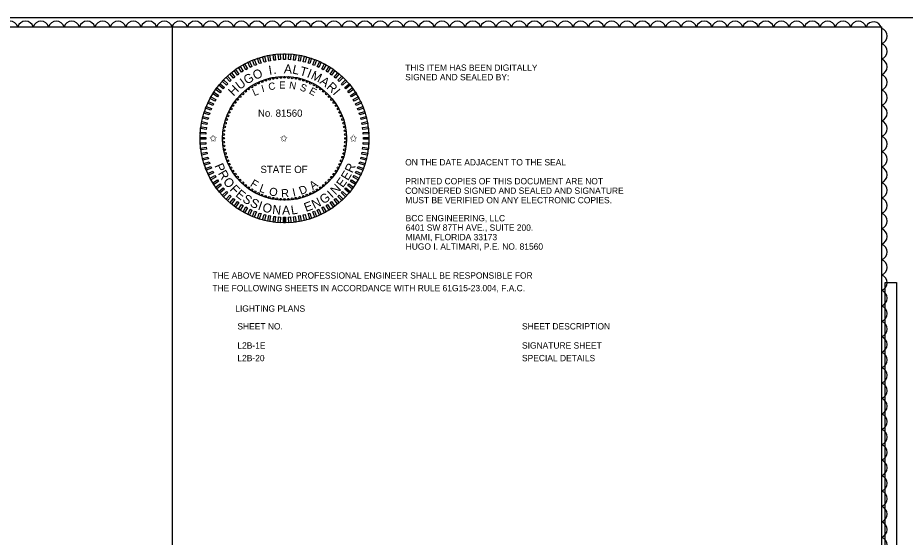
# Model space of a CAD drawing. Extents: x -816.9 to -790.1, y -2199.5 to -2188.9.
# Drawn here: x -804.97 to -795.12, y -2194.66 to -2188.9 of the extents above; entities that cross this region are included whole.
import ezdxf

# ---------------------------------------------------------------- set-up
doc = ezdxf.new("R2010")
doc.units = 0
for name, color, linetype in [('Cloud_dp', 7, 'Continuous'), ('Logo_dp', 7, 'Continuous'), ('NonPlottingEle_dp', 7, 'Continuous'), ('PlotBorder_dp', 7, 'Continuous'), ('ScratchEle_dp', 7, 'Continuous'), ('SheetBorder_dp', 7, 'Continuous'), ('TextMisc', 7, 'Continuous'), ('TextNotes', 7, 'Continuous')]:
    doc.layers.add(name, color=color, linetype=linetype)

msp = doc.modelspace()

# ---------------------------------------------------------------- linework, layer by layer
at = {"layer": 'Cloud_dp'}
for centre, radius, start, end in [((-805.0532, -2189.0276), 0.0897, 17.5, 162.5), ((-804.882, -2189.0276), 0.0897, 17.5, 162.5), ((-804.7109, -2189.0276), 0.0897, 17.5, 162.5), ((-804.5398, -2189.0276), 0.0897, 17.5, 162.5), ((-804.3687, -2189.0276), 0.0897, 17.5, 162.5), ((-804.1976, -2189.0276), 0.0897, 17.5, 162.5), ((-804.0264, -2189.0276), 0.0897, 17.5, 162.5), ((-803.8553, -2189.0276), 0.0897, 17.5, 162.5), ((-803.6842, -2189.0276), 0.0897, 17.5, 162.5), ((-803.5131, -2189.0276), 0.0897, 17.5, 162.5), ((-803.3419, -2189.0276), 0.0897, 17.5, 162.5), ((-803.1708, -2189.0276), 0.0897, 17.5, 162.5), ((-802.9997, -2189.0276), 0.0897, 17.5, 162.5), ((-802.8286, -2189.0276), 0.0897, 17.5, 162.5), ((-802.6575, -2189.0276), 0.0897, 17.5, 162.5), ((-802.4863, -2189.0276), 0.0897, 17.5, 162.5), ((-802.3152, -2189.0276), 0.0897, 17.5, 162.5), ((-802.1441, -2189.0276), 0.0897, 17.5, 162.5), ((-801.973, -2189.0276), 0.0897, 17.5, 162.5), ((-801.8018, -2189.0276), 0.0897, 17.5, 162.5), ((-801.6307, -2189.0276), 0.0897, 17.5, 162.5), ((-801.4596, -2189.0276), 0.0897, 17.5, 162.5), ((-801.2885, -2189.0276), 0.0897, 17.5, 162.5), ((-801.1174, -2189.0276), 0.0897, 17.5, 162.5), ((-800.9462, -2189.0276), 0.0897, 17.5, 162.5), ((-800.7751, -2189.0276), 0.0897, 17.5, 162.5), ((-800.604, -2189.0276), 0.0897, 17.5, 162.5), ((-800.4329, -2189.0276), 0.0897, 17.5, 162.5), ((-800.2617, -2189.0276), 0.0897, 17.5, 162.5), ((-800.0906, -2189.0276), 0.0897, 17.5, 162.5), ((-799.9195, -2189.0276), 0.0897, 17.5, 162.5), ((-799.7484, -2189.0276), 0.0897, 17.5, 162.5), ((-799.5772, -2189.0276), 0.0897, 17.5, 162.5), ((-799.4061, -2189.0276), 0.0897, 17.5, 162.5), ((-799.235, -2189.0276), 0.0897, 17.5, 162.5), ((-799.0639, -2189.0276), 0.0897, 17.5, 162.5), ((-798.8928, -2189.0276), 0.0897, 17.5, 162.5), ((-798.7216, -2189.0276), 0.0897, 17.5, 162.5), ((-798.5505, -2189.0276), 0.0897, 17.5, 162.5), ((-798.3794, -2189.0276), 0.0897, 17.5, 162.5), ((-798.2083, -2189.0276), 0.0897, 17.5, 162.5), ((-798.0371, -2189.0276), 0.0897, 17.5, 162.5), ((-797.866, -2189.0276), 0.0897, 17.5, 162.5), ((-797.6949, -2189.0276), 0.0897, 17.5, 162.5), ((-797.5238, -2189.0276), 0.0897, 17.5, 162.5), ((-797.3527, -2189.0276), 0.0897, 17.5, 162.5), ((-797.1815, -2189.0276), 0.0897, 17.5, 162.5), ((-797.0104, -2189.0276), 0.0897, 17.5, 162.5), ((-796.8393, -2189.0276), 0.0897, 17.5, 162.5), ((-796.6682, -2189.0276), 0.0897, 17.5, 162.5), ((-796.497, -2189.0276), 0.0897, 17.5, 162.5), ((-796.3259, -2189.0276), 0.0897, 17.5, 162.5), ((-796.1548, -2189.0276), 0.0897, 17.5, 162.5), ((-795.9837, -2189.0276), 0.0897, 17.5, 162.5), ((-795.8126, -2189.0276), 0.0897, 17.5, 162.5), ((-795.6414, -2189.0276), 0.0897, 17.5, 162.5), ((-795.4735, -2189.036), 0.0896, 11.74536, 156.74536), ((-795.4127, -2189.1033), 0.0897, 287.5, 72.5), ((-795.4127, -2189.2745), 0.0897, 287.5, 72.5), ((-795.4127, -2189.4456), 0.0897, 287.5, 72.5), ((-795.4127, -2189.6167), 0.0897, 287.5, 72.5), ((-795.4127, -2189.7878), 0.0897, 287.5, 72.5), ((-795.4127, -2189.959), 0.0897, 287.5, 72.5), ((-795.4127, -2190.1301), 0.0897, 287.5, 72.5), ((-795.4127, -2190.3012), 0.0897, 287.5, 72.5), ((-795.4127, -2190.4723), 0.0897, 287.5, 72.5), ((-795.4127, -2190.6434), 0.0897, 287.5, 72.5), ((-795.4127, -2190.8146), 0.0897, 287.5, 72.5), ((-795.4127, -2190.9857), 0.0897, 287.5, 72.5), ((-795.4127, -2191.1568), 0.0897, 287.5, 72.5), ((-795.4127, -2191.3279), 0.0897, 287.5, 72.5), ((-795.4127, -2191.4991), 0.0897, 287.5, 72.5), ((-795.4127, -2191.6702), 0.0897, 287.5, 72.5), ((-795.4127, -2191.8413), 0.0897, 287.5, 72.5), ((-795.4127, -2192.0124), 0.0897, 287.5, 72.5), ((-795.4127, -2192.1835), 0.0897, 287.5, 72.5), ((-795.4127, -2192.3547), 0.0897, 287.5, 72.5), ((-795.4127, -2192.5258), 0.0897, 287.5, 72.5), ((-795.4127, -2192.6969), 0.0897, 287.5, 72.5), ((-795.4127, -2192.868), 0.0897, 287.5, 72.5), ((-795.4127, -2193.0392), 0.0897, 287.5, 72.5), ((-795.4127, -2193.2103), 0.0897, 287.5, 72.5), ((-795.4127, -2193.3814), 0.0897, 287.5, 72.5), ((-795.4127, -2193.5525), 0.0897, 287.5, 72.5), ((-795.4127, -2193.7237), 0.0897, 287.5, 72.5), ((-795.4127, -2193.8948), 0.0897, 287.5, 72.5), ((-795.4127, -2194.0659), 0.0897, 287.5, 72.5), ((-795.4127, -2194.237), 0.0897, 287.5, 72.5), ((-795.4127, -2194.4081), 0.0897, 287.5, 72.5), ((-795.4127, -2194.5793), 0.0897, 287.5, 72.5), ((-795.4127, -2194.7504), 0.0897, 287.5, 72.5)]:
    msp.add_arc(centre, radius, start, end, dxfattribs=at)
at = {"layer": 'Logo_dp'}
for p, q in [((-802.0181, -2191.1759), (-802.0183, -2191.1134)), ((-802.0081, -2191.1758), (-802.0083, -2191.1134)), ((-801.9981, -2191.1758), (-801.9983, -2191.1133))]:
    msp.add_line(p, q, dxfattribs=at)
for points in [[(-802.2687, -2189.4037), (-802.2879, -2189.4099), (-802.3072, -2189.3506), (-802.288, -2189.3443)], [(-802.2158, -2189.389), (-802.2353, -2189.394), (-802.2508, -2189.3335), (-802.2313, -2189.3285)], [(-802.162, -2189.3776), (-802.1818, -2189.3814), (-802.1935, -2189.3201), (-802.1737, -2189.3163)], [(-802.1076, -2189.3696), (-802.1277, -2189.3722), (-802.1355, -2189.3102), (-802.1155, -2189.3077)], [(-802.0529, -2189.3651), (-802.073, -2189.3664), (-802.0769, -2189.3041), (-802.0568, -2189.3028)], [(-801.9979, -2189.364), (-802.0181, -2189.364), (-802.0181, -2189.3016), (-801.9979, -2189.3016)], [(-801.943, -2189.3664), (-801.9632, -2189.3651), (-801.9592, -2189.3028), (-801.9391, -2189.3041)], [(-801.8884, -2189.3722), (-801.9084, -2189.3697), (-801.9006, -2189.3077), (-801.8806, -2189.3103)], [(-801.8342, -2189.3814), (-801.854, -2189.3776), (-801.8423, -2189.3163), (-801.8225, -2189.3201)], [(-801.7807, -2189.394), (-801.8003, -2189.389), (-801.7847, -2189.3286), (-801.7652, -2189.3336)], [(-801.7281, -2189.41), (-801.7473, -2189.4037), (-801.728, -2189.3444), (-801.7088, -2189.3506)], [(-802.4682, -2189.4947), (-802.4852, -2189.5055), (-802.5187, -2189.4528), (-802.5016, -2189.442)], [(-802.4206, -2189.4673), (-802.4382, -2189.477), (-802.4683, -2189.4223), (-802.4506, -2189.4126)], [(-802.3713, -2189.4429), (-802.3896, -2189.4515), (-802.4161, -2189.395), (-802.3979, -2189.3865)], [(-802.3206, -2189.4217), (-802.3394, -2189.4291), (-802.3624, -2189.3711), (-802.3436, -2189.3637)], [(-801.6766, -2189.4292), (-801.6954, -2189.4218), (-801.6724, -2189.3637), (-801.6537, -2189.3712)], [(-801.6265, -2189.4516), (-801.6447, -2189.443), (-801.6182, -2189.3865), (-801.5999, -2189.3951)], [(-801.5778, -2189.4771), (-801.5955, -2189.4674), (-801.5654, -2189.4127), (-801.5477, -2189.4224)], [(-801.5308, -2189.5056), (-801.5479, -2189.4948), (-801.5144, -2189.4421), (-801.4974, -2189.4529)], [(-802.5994, -2189.5941), (-802.6142, -2189.6079), (-802.6569, -2189.5624), (-802.6422, -2189.5486)], [(-802.5578, -2189.5583), (-802.5734, -2189.5711), (-802.6131, -2189.523), (-802.5976, -2189.5102)], [(-802.514, -2189.5251), (-802.5303, -2189.5369), (-802.567, -2189.4865), (-802.5507, -2189.4746)], [(-801.4857, -2189.5371), (-801.5021, -2189.5252), (-801.4654, -2189.4747), (-801.4491, -2189.4866)], [(-801.4427, -2189.5712), (-801.4583, -2189.5584), (-801.4185, -2189.5103), (-801.4029, -2189.5231)], [(-801.4019, -2189.6081), (-801.4166, -2189.5942), (-801.3739, -2189.5487), (-801.3592, -2189.5626)], [(-802.6756, -2189.6733), (-802.6884, -2189.6889), (-802.7365, -2189.6491), (-802.7237, -2189.6335)], [(-802.6388, -2189.6325), (-802.6526, -2189.6472), (-802.6981, -2189.6045), (-802.6843, -2189.5898)], [(-801.3635, -2189.6474), (-801.3773, -2189.6327), (-801.3318, -2189.5899), (-801.318, -2189.6046)], [(-801.3277, -2189.689), (-801.3405, -2189.6735), (-801.2924, -2189.6337), (-801.2796, -2189.6492)], [(-802.7412, -2189.7614), (-802.752, -2189.7785), (-802.8047, -2189.745), (-802.7939, -2189.728)], [(-802.7098, -2189.7163), (-802.7216, -2189.7327), (-802.7721, -2189.696), (-802.7602, -2189.6797)], [(-801.2945, -2189.7328), (-801.3064, -2189.7165), (-801.2559, -2189.6798), (-801.244, -2189.6961)], [(-801.2641, -2189.7786), (-801.2749, -2189.7616), (-801.2222, -2189.7281), (-801.2114, -2189.7452)], [(-802.7952, -2189.8571), (-802.8038, -2189.8753), (-802.8603, -2189.8488), (-802.8517, -2189.8305)], [(-802.7697, -2189.8084), (-802.7794, -2189.8261), (-802.8341, -2189.796), (-802.8244, -2189.7783)], [(-801.2367, -2189.8262), (-801.2464, -2189.8086), (-801.1917, -2189.7785), (-801.182, -2189.7962)], [(-801.2123, -2189.8755), (-801.2209, -2189.8572), (-801.1645, -2189.8307), (-801.1559, -2189.8489)], [(-802.8368, -2189.9587), (-802.8431, -2189.9779), (-802.9024, -2189.9586), (-802.8962, -2189.9394)], [(-802.8176, -2189.9072), (-802.825, -2189.926), (-802.8831, -2189.903), (-802.8756, -2189.8843)], [(-801.1911, -2189.9262), (-801.1985, -2189.9074), (-801.1405, -2189.8844), (-801.1331, -2189.9032)], [(-801.1731, -2189.9781), (-801.1793, -2189.9589), (-801.12, -2189.9396), (-801.1137, -2189.9588)], [(-802.8528, -2190.0113), (-802.8578, -2190.0309), (-802.9182, -2190.0153), (-802.9132, -2189.9958)], [(-801.1584, -2190.031), (-801.1634, -2190.0115), (-801.1029, -2189.996), (-801.0979, -2190.0155)], [(-802.8746, -2190.119), (-802.8771, -2190.139), (-802.9391, -2190.1312), (-802.9365, -2190.1112)], [(-802.8654, -2190.0648), (-802.8692, -2190.0846), (-802.9305, -2190.0729), (-802.9267, -2190.0531)], [(-801.147, -2190.0848), (-801.1508, -2190.065), (-801.0895, -2190.0533), (-801.0857, -2190.0731)], [(-801.139, -2190.1392), (-801.1416, -2190.1192), (-801.0797, -2190.1113), (-801.0771, -2190.1314)], [(-802.8828, -2190.2285), (-802.8828, -2190.2487), (-802.9452, -2190.2487), (-802.9452, -2190.2285)], [(-802.8804, -2190.1736), (-802.8817, -2190.1938), (-802.944, -2190.1898), (-802.9427, -2190.1697)], [(-801.1345, -2190.1939), (-801.1358, -2190.1738), (-801.0735, -2190.1699), (-801.0722, -2190.19)], [(-801.1334, -2190.2489), (-801.1334, -2190.2287), (-801.071, -2190.2287), (-801.071, -2190.2489)], [(-802.8817, -2190.2835), (-802.8804, -2190.3036), (-802.9427, -2190.3075), (-802.944, -2190.2874)], [(-802.8772, -2190.3382), (-802.8746, -2190.3582), (-802.9366, -2190.3661), (-802.9391, -2190.3461)], [(-801.1416, -2190.3584), (-801.1391, -2190.3384), (-801.0771, -2190.3462), (-801.0797, -2190.3663)], [(-801.1358, -2190.3038), (-801.1345, -2190.2836), (-801.0722, -2190.2876), (-801.0735, -2190.3077)], [(-802.8692, -2190.3926), (-802.8654, -2190.4124), (-802.9267, -2190.4241), (-802.9305, -2190.4043)], [(-801.1508, -2190.4126), (-801.147, -2190.3928), (-801.0857, -2190.4045), (-801.0895, -2190.4243)], [(-802.8578, -2190.4464), (-802.8528, -2190.4659), (-802.9133, -2190.4814), (-802.9183, -2190.4619)], [(-802.8431, -2190.4993), (-802.8369, -2190.5185), (-802.8962, -2190.5378), (-802.9025, -2190.5186)], [(-801.1794, -2190.5187), (-801.1731, -2190.4995), (-801.1138, -2190.5188), (-801.12, -2190.538)], [(-801.1634, -2190.4661), (-801.1584, -2190.4465), (-801.098, -2190.4621), (-801.103, -2190.4816)], [(-802.8251, -2190.5512), (-802.8177, -2190.57), (-802.8757, -2190.593), (-802.8831, -2190.5742)], [(-802.8039, -2190.6019), (-802.7953, -2190.6202), (-802.8518, -2190.6467), (-802.8604, -2190.6285)], [(-801.221, -2190.6203), (-801.2124, -2190.6021), (-801.1559, -2190.6287), (-801.1645, -2190.6469)], [(-801.1986, -2190.5702), (-801.1912, -2190.5514), (-801.1331, -2190.5744), (-801.1406, -2190.5931)], [(-802.7795, -2190.6512), (-802.7698, -2190.6688), (-802.8245, -2190.6989), (-802.8342, -2190.6812)], [(-802.7521, -2190.6988), (-802.7413, -2190.7158), (-802.794, -2190.7493), (-802.8048, -2190.7322)], [(-801.275, -2190.716), (-801.2642, -2190.6989), (-801.2115, -2190.7324), (-801.2223, -2190.7494)], [(-801.2465, -2190.669), (-801.2368, -2190.6513), (-801.1821, -2190.6814), (-801.1918, -2190.6991)], [(-802.7217, -2190.7446), (-802.7099, -2190.7609), (-802.7604, -2190.7976), (-802.7722, -2190.7813)], [(-802.6886, -2190.7884), (-802.6757, -2190.8039), (-802.7238, -2190.8437), (-802.7366, -2190.8282)], [(-802.6527, -2190.83), (-802.6389, -2190.8447), (-802.6844, -2190.8875), (-802.6982, -2190.8728)], [(-801.3775, -2190.8449), (-801.3637, -2190.8302), (-801.3182, -2190.8729), (-801.332, -2190.8876)], [(-801.3406, -2190.8041), (-801.3278, -2190.7885), (-801.2797, -2190.8283), (-801.2926, -2190.8439)], [(-801.3065, -2190.7611), (-801.2946, -2190.7447), (-801.2441, -2190.7814), (-801.256, -2190.7978)], [(-802.6143, -2190.8693), (-802.5996, -2190.8832), (-802.6423, -2190.9287), (-802.657, -2190.9148)], [(-802.5735, -2190.9062), (-802.5579, -2190.919), (-802.5977, -2190.9671), (-802.6133, -2190.9543)], [(-801.4584, -2190.9191), (-801.4429, -2190.9063), (-801.4031, -2190.9544), (-801.4186, -2190.9672)], [(-801.4168, -2190.8833), (-801.4021, -2190.8695), (-801.3593, -2190.915), (-801.374, -2190.9288)], [(-802.5305, -2190.9403), (-802.5141, -2190.9522), (-802.5508, -2191.0027), (-802.5672, -2190.9908)], [(-802.4854, -2190.9718), (-802.4683, -2190.9826), (-802.5018, -2191.0353), (-802.5188, -2191.0245)], [(-802.4384, -2191.0003), (-802.4207, -2191.01), (-802.4508, -2191.0647), (-802.4685, -2191.055)], [(-802.3897, -2191.0258), (-802.3715, -2191.0344), (-802.3981, -2191.0909), (-802.4163, -2191.0823)], [(-801.6449, -2191.0345), (-801.6266, -2191.0259), (-801.6001, -2191.0824), (-801.6183, -2191.0909)], [(-801.5957, -2191.0101), (-801.578, -2191.0004), (-801.5479, -2191.0551), (-801.5656, -2191.0648)], [(-801.548, -2190.9827), (-801.531, -2190.9719), (-801.4975, -2191.0246), (-801.5146, -2191.0354)], [(-801.5022, -2190.9523), (-801.4859, -2190.9405), (-801.4492, -2190.991), (-801.4655, -2191.0028)], [(-802.3396, -2191.0482), (-802.3208, -2191.0556), (-802.3438, -2191.1137), (-802.3625, -2191.1062)], [(-802.2881, -2191.0674), (-802.2689, -2191.0737), (-802.2882, -2191.133), (-802.3074, -2191.1268)], [(-802.2355, -2191.0834), (-802.216, -2191.0884), (-802.2315, -2191.1488), (-802.251, -2191.1438)], [(-802.182, -2191.096), (-802.1622, -2191.0998), (-802.1739, -2191.1611), (-802.1937, -2191.1573)], [(-802.1278, -2191.1052), (-802.1078, -2191.1077), (-802.1156, -2191.1697), (-802.1357, -2191.1671)], [(-802.0732, -2191.111), (-802.0531, -2191.1123), (-802.057, -2191.1746), (-802.0771, -2191.1733)], [(-802.0183, -2191.1134), (-801.9981, -2191.1134), (-801.9981, -2191.1758), (-802.0183, -2191.1758)], [(-801.9633, -2191.1123), (-801.9432, -2191.111), (-801.9393, -2191.1733), (-801.9594, -2191.1746)], [(-801.9086, -2191.1078), (-801.8886, -2191.1052), (-801.8807, -2191.1672), (-801.9008, -2191.1697)], [(-801.8542, -2191.0998), (-801.8344, -2191.096), (-801.8227, -2191.1573), (-801.8425, -2191.1611)], [(-801.8004, -2191.0884), (-801.7809, -2191.0834), (-801.7654, -2191.1439), (-801.7849, -2191.1489)], [(-801.7475, -2191.0737), (-801.7283, -2191.0675), (-801.709, -2191.1268), (-801.7282, -2191.1331)], [(-801.6956, -2191.0557), (-801.6768, -2191.0483), (-801.6538, -2191.1063), (-801.6726, -2191.1137)]]:
    msp.add_lwpolyline(points, close=True, dxfattribs=at)
for centre in [(-802.0501, -2189.5628), (-802.0075, -2189.5615), (-801.965, -2189.5629), (-802.3339, -2189.645), (-802.2959, -2189.6257), (-802.2569, -2189.6089), (-802.2168, -2189.5945), (-802.176, -2189.5826), (-802.1344, -2189.5734), (-802.0924, -2189.5668), (-801.9227, -2189.5669), (-801.8807, -2189.5736), (-801.8391, -2189.5829), (-801.7983, -2189.5948), (-801.7583, -2189.6093), (-801.7193, -2189.6262), (-801.6814, -2189.6455), (-802.4713, -2189.7447), (-802.4393, -2189.7166), (-802.4057, -2189.6905), (-802.3705, -2189.6666), (-801.6448, -2189.6672), (-801.6096, -2189.6912), (-801.576, -2189.7173), (-801.5441, -2189.7454), (-802.5556, -2189.8402), (-802.5295, -2189.8066), (-802.5014, -2189.7747), (-801.5141, -2189.7755), (-801.486, -2189.8075), (-801.4599, -2189.8411), (-802.6206, -2189.9499), (-802.6013, -2189.912), (-802.5796, -2189.8754), (-801.436, -2189.8763), (-801.4144, -2189.913), (-801.3951, -2189.9509), (-802.652, -2190.0289), (-802.6375, -2189.9889), (-801.3783, -2189.9899), (-801.3639, -2190.03), (-802.6799, -2190.1533), (-802.6732, -2190.1113), (-802.6639, -2190.0697), (-801.352, -2190.0708), (-801.3428, -2190.1124), (-801.3362, -2190.1544), (-802.6853, -2190.2381), (-802.6839, -2190.1956), (-801.3322, -2190.1967), (-801.3309, -2190.2393), (-802.684, -2190.2807), (-802.68, -2190.323), (-801.3363, -2190.3241), (-801.3323, -2190.2818), (-802.6734, -2190.365), (-802.6642, -2190.4066), (-802.6523, -2190.4474), (-801.3642, -2190.4485), (-801.3523, -2190.4077), (-801.343, -2190.3662), (-802.638, -2190.4875), (-802.6211, -2190.5265), (-801.3956, -2190.5275), (-801.3787, -2190.4885), (-802.6018, -2190.5645), (-802.5802, -2190.6011), (-802.5563, -2190.6363), (-801.4606, -2190.6372), (-801.4366, -2190.602), (-801.4149, -2190.5654), (-802.5303, -2190.6699), (-802.5021, -2190.7019), (-802.4721, -2190.732), (-801.5449, -2190.7327), (-801.5148, -2190.7027), (-801.4867, -2190.6708), (-802.4402, -2190.7601), (-802.4066, -2190.7862), (-802.3714, -2190.8102), (-802.3348, -2190.8319), (-801.6824, -2190.8324), (-801.6457, -2190.8108), (-801.6105, -2190.7869), (-801.5769, -2190.7609), (-802.297, -2190.8512), (-802.2579, -2190.8681), (-802.2179, -2190.8826), (-802.1771, -2190.8945), (-802.1356, -2190.9038), (-802.0935, -2190.9105), (-802.0512, -2190.9145), (-802.0081, -2190.9159), (-801.9661, -2190.9146), (-801.9238, -2190.9106), (-801.8818, -2190.904), (-801.8402, -2190.8948), (-801.7994, -2190.8829), (-801.7593, -2190.8686), (-801.7203, -2190.8517)]:
    msp.add_circle(centre, 0.01, dxfattribs=at)
at = {"layer": 'NonPlottingEle_dp'}
for radius in [0.9371, 0.6872]:
    msp.add_circle((-802.0081, -2190.2387), radius, dxfattribs=at)
at = {"layer": 'PlotBorder_dp'}
msp.add_lwpolyline([(-811.3358, -2199.5006), (-794.8358, -2199.5006), (-794.8358, -2188.9006), (-811.3358, -2188.9006)], close=True, dxfattribs=at)
at = {"layer": 'ScratchEle_dp'}
msp.add_lwpolyline([(-795.3456, -2191.8382), (-795.218, -2191.8382), (-795.218, -2198.6801), (-795.3456, -2198.6801)], close=True, dxfattribs=at)
at = {"layer": 'SheetBorder_dp'}
for p, q in [((-810.7858, -2189.0006), (-795.3858, -2189.0006)), ((-803.2512, -2198.5798), (-803.2512, -2188.9798)), ((-795.3858, -2189.0006), (-795.3858, -2199.4006))]:
    msp.add_line(p, q, dxfattribs=at)

# ---------------------------------------------------------------- texts
at = {"layer": 'Logo_dp'}
for s, rotation, p in [('I', 14.81888, (-802.2533, -2189.7284)), ('C', 8.98261, (-802.1808, -2189.7058)), ('E', 359.96623, (-802.0681, -2189.6869)), ('N', 350.64643, (-801.9613, -2189.6854)), ('S', 341.03996, (-801.8442, -2189.7042)), ('L', 23.30524, (-802.3439, -2189.7713)), ('E', 331.16864, (-801.7428, -2189.7368))]:
    msp.add_text(s, height=0.08, rotation=rotation, dxfattribs=at).set_placement(p)
for p in [(-802.8427, -2190.2766), (-802.0583, -2190.2766), (-801.2868, -2190.2766)]:
    msp.add_text('✩', height=0.08, dxfattribs=at).set_placement(p)
at = {"layer": 'TextMisc'}
for s, height, rotation, p in [('I', 0.1, 8.98261, (-802.177, -2189.5347)), ('A', 0.1, 356.89262, (-802.0166, -2189.516)), ('L', 0.1, 347.47515, (-801.9271, -2189.5178)), ('T', 0.1, 344.27273, (-801.8472, -2189.5346)), ('G', 0.1, 28.78207, (-802.4288, -2189.6438)), ('O', 0.1, 23.30524, (-802.3352, -2189.5922)), ('.', 0.1, 6.01169, (-802.1308, -2189.5261)), ('I', 0.1, 337.77772, (-801.7672, -2189.5574)), ('M', 0.1, 334.48695, (-801.724, -2189.5742)), ('H', 0.1, 44.34211, (-802.5748, -2189.7762)), ('U', 0.1, 36.72494, (-802.5049, -2189.7043)), ('A', 0.1, 324.45371, (-801.6249, -2189.6237)), ('R', 0.1, 317.64216, (-801.5485, -2189.6777)), ('I', 0.1, 310.74416, (-801.4788, -2189.7416)), ('P', 0.1, 293.19548, (-802.7866, -2190.5413)), ('R', 0.1, 65.28865, (-801.2551, -2190.6307)), ('R', 0.1, 300.25949, (-802.7497, -2190.6272)), ('E', 0.1, 58.61694, (-801.3043, -2190.7146)), ('O', 0.1, 307.26617, (-802.6956, -2190.719)), ('F', 0.09, 328.53399, (-802.3964, -2190.7642)), ('A', 0.09, 35.54629, (-801.6939, -2190.8134)), ('E', 0.1, 53.99864, (-801.3615, -2190.7933)), ('F', 0.1, 314.20329, (-802.6222, -2190.8115)), ('E', 0.1, 321.0594, (-802.5589, -2190.875)), ('L', 0.09, 339.48752, (-802.2953, -2190.8271)), ('O', 0.09, 348.08156, (-802.1858, -2190.8677)), ('R', 0.09, 3.10738, (-802.0438, -2190.8939)), ('I', 0.09, 12.52485, (-801.9096, -2190.8848)), ('D', 0.09, 22.22228, (-801.8255, -2190.8679)), ('I', 0.1, 41.83906, (-801.4809, -2190.9074)), ('N', 0.1, 44.34211, (-801.4415, -2190.8731)), ('S', 0.1, 327.82385, (-802.4827, -2190.9355)), ('S', 0.1, 334.48695, (-802.3996, -2190.9869)), ('E', 0.1, 20.51248, (-801.7696, -2191.0568)), ('N', 0.1, 26.0618, (-801.6781, -2191.0235)), ('G', 0.1, 34.11362, (-801.5769, -2190.9733)), ('I', 0.1, 341.03996, (-802.311, -2191.0282)), ('O', 0.1, 344.27273, (-802.2619, -2191.0458)), ('N', 0.1, 353.78581, (-802.1476, -2191.0757)), ('A', 0.1, 359.96623, (-802.0353, -2191.0867)), ('L', 0.1, 8.98261, (-801.9297, -2191.0858))]:
    msp.add_text(s, height=height, rotation=rotation, dxfattribs=at).set_placement(p)
for s, height, p in [('THIS ITEM HAS BEEN DIGITALLY', 0.07, (-800.6693, -2189.4894)), ('SIGNED AND SEALED BY:', 0.07, (-800.6693, -2189.5944)), ('No. 81560', 0.07997, (-802.3027, -2189.9992)), ('ON THE DATE ADJACENT TO THE SEAL', 0.07, (-800.6693, -2190.5394)), ('STATE OF', 0.07997, (-802.275, -2190.6232)), ('PRINTED COPIES OF THIS DOCUMENT ARE NOT ', 0.07, (-800.6693, -2190.7494)), ('CONSIDERED SIGNED AND SEALED AND SIGNATURE ', 0.07, (-800.6693, -2190.8544)), ('MUST BE VERIFIED ON ANY ELECTRONIC COPIES.', 0.07, (-800.6693, -2190.9594)), ('BCC ENGINEERING, LLC', 0.07, (-800.6643, -2191.1592)), ('6401 SW 87TH AVE., SUITE 200.', 0.07, (-800.6643, -2191.2642)), ('MIAMI, FLORIDA 33173', 0.07, (-800.6643, -2191.3692)), ('HUGO I. ALTIMARI, P.E. NO. 81560', 0.07, (-800.6643, -2191.4742)), ('THE ABOVE NAMED PROFESSIONAL ENGINEER SHALL BE RESPONSIBLE FOR ', 0.07, (-802.8084, -2191.7953)), ('THE FOLLOWING SHEETS IN ACCORDANCE WITH RULE 61G15-23.004, F.A.C.', 0.07, (-802.8084, -2191.9353)), ('LIGHTING PLANS', 0.07, (-802.5547, -2192.1624))]:
    msp.add_text(s, height=height, dxfattribs=at).set_placement(p)
at = {"layer": 'TextNotes'}
for s, p in [('SHEET NO.', (-802.5312, -2192.3594)), ('SHEET DESCRIPTION', (-799.3737, -2192.3594)), ('L2B-1E', (-802.5312, -2192.5717)), ('SIGNATURE SHEET', (-799.3737, -2192.5716)), ('L2B-20', (-802.5312, -2192.7117)), ('SPECIAL DETAILS', (-799.3737, -2192.7116))]:
    msp.add_text(s, height=0.07, dxfattribs=at).set_placement(p)

doc.saveas('drawing.dxf')
